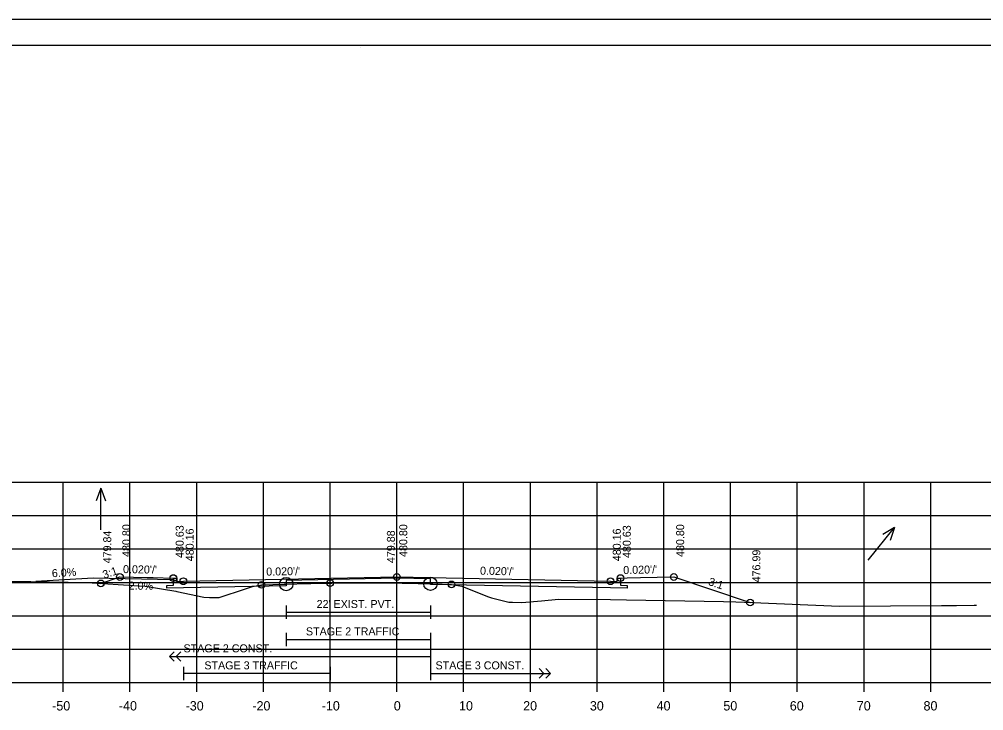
# Model space of a CAD drawing. Extents: x 1371057 to 1372761, y 380005 to 390517.
# Drawn here: x 1371504.3 to 1371648.8, y 382034.9 to 382138.5 of the extents above; entities that cross this region are included whole.
import ezdxf

# ---------------------------------------------------------------- set-up
doc = ezdxf.new("R2010")
doc.units = 0
for name, color, linetype in [('R_Alt Surface', 7, 'Continuous'), ('R_Axis', 7, 'Continuous'), ('R_Axis Annot', 7, 'Continuous'), ('R_Border', 7, 'Continuous'), ('R_Drive', 7, 'Continuous'), ('R_Exist Surface', 7, 'Continuous'), ('R_Fin Surface', 7, 'Continuous'), ('R_Grid', 7, 'Continuous'), ('R_No Plot', 7, 'Continuous'), ('R_Striping', 7, 'Continuous'), ('R_Water', 7, 'Continuous'), ('R_Water Annot', 7, 'Continuous'), ('R_Xsect Elev', 7, 'Continuous'), ('R_Xsect Slope', 7, 'Continuous')]:
    doc.layers.add(name, color=color, linetype=linetype)

msp = doc.modelspace()

# ---------------------------------------------------------------- linework, layer by layer
at = {"layer": 'R_Alt Surface'}
for points in [[(1371594.37, 382054.74), (1371594.37, 382053.66), (1371595.37, 382053.64), (1371595.37, 382053.21), (1371592.87, 382053.26), (1371565.89, 382053.8), (1371565.89, 382054.63), (1371560.87, 382054.73), (1371544.28, 382054.39), (1371544.28, 382053.56), (1371528.87, 382053.26), (1371526.37, 382053.21), (1371526.37, 382053.64), (1371527.37, 382053.66), (1371527.37, 382054.74)], [(1371594.37, 382054.74), (1371594.37, 382053.66), (1371595.37, 382053.64), (1371595.37, 382053.21), (1371592.87, 382053.26), (1371565.89, 382053.8), (1371565.89, 382054.63), (1371560.87, 382054.73), (1371544.28, 382054.39), (1371544.28, 382053.56), (1371528.87, 382053.26), (1371526.37, 382053.21), (1371526.37, 382053.64), (1371527.37, 382053.66), (1371527.37, 382054.74)], [(1371544.28, 382050.65), (1371544.28, 382048.65)], [(1371565.89, 382050.65), (1371565.89, 382048.65)], [(1371544.28, 382049.65), (1371565.89, 382049.65)]]:
    msp.add_lwpolyline(points, dxfattribs=at)
at = {"layer": 'R_Axis'}
for p, q in [((1371410.87, 382039.1), (1371710.87, 382039.1)), ((1371510.87, 382037.7), (1371510.87, 382039.1)), ((1371520.87, 382037.7), (1371520.87, 382039.1)), ((1371530.87, 382037.7), (1371530.87, 382039.1)), ((1371540.87, 382037.7), (1371540.87, 382039.1)), ((1371550.87, 382037.7), (1371550.87, 382039.1)), ((1371560.87, 382037.7), (1371560.87, 382039.1)), ((1371570.87, 382037.7), (1371570.87, 382039.1)), ((1371580.87, 382037.7), (1371580.87, 382039.1)), ((1371590.87, 382037.7), (1371590.87, 382039.1)), ((1371600.87, 382037.7), (1371600.87, 382039.1)), ((1371610.87, 382037.7), (1371610.87, 382039.1)), ((1371620.87, 382037.7), (1371620.87, 382039.1)), ((1371630.87, 382037.7), (1371630.87, 382039.1)), ((1371640.87, 382037.7), (1371640.87, 382039.1))]:
    msp.add_line(p, q, dxfattribs=at)
at = {"layer": 'R_Border'}
for p, q in [((1371402.87, 382134.56), (1371719.05, 382134.56)), ((1371555.39, 382134.3), (1371555.39, 382134.3)), ((1371555.39, 382134.3), (1371555.39, 382134.3))]:
    msp.add_line(p, q, dxfattribs=at)
at = {"layer": 'R_Drive'}
for p, q in [((1371515.38, 382054.73), (1371506.76, 382054.21)), ((1371527.38, 382054.49), (1371515.38, 382054.73)), ((1371527.88, 382054.24), (1371527.38, 382054.49))]:
    msp.add_line(p, q, dxfattribs=at)
at = {"layer": 'R_Exist Surface'}
msp.add_lwpolyline([(1371491.95, 382054.47), (1371514.43, 382054.07), (1371522.27, 382053.59), (1371523.14, 382053.54), (1371527.75, 382052.76), (1371527.87, 382052.74), (1371527.88, 382052.73), (1371527.9, 382052.73), (1371531.96, 382051.86), (1371532.79, 382051.85), (1371534.22, 382051.81), (1371538.19, 382053.15), (1371538.92, 382053.38), (1371539.24, 382053.46), (1371540.59, 382053.72), (1371543.96, 382053.83), (1371544.28, 382053.84), (1371544.37, 382053.84), (1371547.41, 382053.94), (1371547.99, 382053.95), (1371554.32, 382054.04), (1371554.41, 382054.04), (1371555.14, 382054.03), (1371555.14, 382054.03), (1371555.64, 382054.03), (1371561.66, 382053.97), (1371562.16, 382053.96), (1371565.89, 382053.88), (1371565.89, 382053.88), (1371566.25, 382053.86), (1371569.06, 382053.79), (1371570.02, 382053.64), (1371570.61, 382053.52), (1371574.43, 382052), (1371575.06, 382051.78), (1371576.06, 382051.53), (1371577.65, 382051.13), (1371578.2, 382051.12), (1371579.6, 382051.06), (1371582.52, 382051.33), (1371585.07, 382051.56), (1371592.86, 382051.54), (1371595.3, 382051.5), (1371609.81, 382051.21), (1371611.64, 382051.18), (1371614.23, 382051.07), (1371627.2, 382050.55), (1371642.46, 382050.62), (1371644.73, 382050.64), (1371647.37, 382050.68), (1371647.74, 382050.68)], dxfattribs=at)
at = {"layer": 'R_Fin Surface'}
msp.add_lwpolyline([(1371516.51, 382053.94), (1371519.37, 382054.9), (1371523.44, 382054.81), (1371524.37, 382054.8), (1371527.37, 382054.74), (1371527.79, 382054.74), (1371527.87, 382054.74), (1371527.88, 382054.24), (1371528.87, 382054.26), (1371560.87, 382054.9), (1371560.87, 382054.9), (1371560.88, 382054.9), (1371592.87, 382054.26), (1371593.21, 382054.25), (1371593.87, 382054.24), (1371593.87, 382054.49), (1371593.87, 382054.74), (1371594.17, 382054.74), (1371594.37, 382054.74), (1371595.38, 382054.76), (1371597.37, 382054.8), (1371597.37, 382054.8), (1371602.37, 382054.9), (1371602.38, 382054.9), (1371613.79, 382051.09)], dxfattribs=at)
at = {"layer": 'R_Grid'}
for p, q in [((1371410.87, 382069.1), (1371710.87, 382069.1)), ((1371510.87, 382039.1), (1371510.87, 382069.1)), ((1371520.87, 382039.1), (1371520.87, 382069.1)), ((1371530.87, 382039.1), (1371530.87, 382069.1)), ((1371540.87, 382039.1), (1371540.87, 382069.1)), ((1371550.87, 382039.1), (1371550.87, 382069.1)), ((1371560.87, 382039.1), (1371560.87, 382069.1)), ((1371570.87, 382039.1), (1371570.87, 382069.1)), ((1371580.87, 382039.1), (1371580.87, 382069.1)), ((1371590.87, 382039.1), (1371590.87, 382069.1)), ((1371600.87, 382039.1), (1371600.87, 382069.1)), ((1371610.87, 382039.1), (1371610.87, 382069.1)), ((1371620.87, 382039.1), (1371620.87, 382069.1)), ((1371630.87, 382039.1), (1371630.87, 382069.1)), ((1371640.87, 382039.1), (1371640.87, 382069.1)), ((1371410.87, 382064.1), (1371710.87, 382064.1)), ((1371410.87, 382059.1), (1371710.87, 382059.1)), ((1371410.87, 382054.1), (1371710.87, 382054.1)), ((1371410.87, 382049.1), (1371710.87, 382049.1)), ((1371410.87, 382044.1), (1371710.87, 382044.1)), ((1371410.87, 382039.1), (1371710.87, 382039.1))]:
    msp.add_line(p, q, dxfattribs=at)
at = {"layer": 'R_No Plot'}
msp.add_line((1371390.47, 382138.46), (1371723.8, 382138.46), dxfattribs=at)
for points in [[(1371390.46, 382138.46), (1371723.8, 382138.46), (1371723.8, 381925.12), (1371390.46, 381925.12)], [(1371636.79, 382134.56), (1371656.41, 382134.56), (1371656.41, 382124.68), (1371672.52, 382124.68), (1371695.72, 382124.68), (1371695.84, 382096.52), (1371719.05, 382096.52), (1371719.05, 381929.1), (1371402.87, 381929.1), (1371402.87, 382134.56)]]:
    msp.add_lwpolyline(points, close=True, dxfattribs=at)
for centre, radius in [((1371516.51, 382053.94), 0.5), ((1371519.37, 382054.9), 0.5), ((1371527.37, 382054.74), 0.5), ((1371528.87, 382054.26), 0.5), ((1371544.28, 382053.84), 1), ((1371550.87, 382053.99), 0.5), ((1371560.87, 382054.9), 0.5), ((1371565.89, 382053.88), 1), ((1371592.87, 382054.26), 0.5), ((1371594.37, 382054.74), 0.5), ((1371602.37, 382054.9), 0.5), ((1371540.59, 382053.72), 0.5), ((1371569.06, 382053.79), 0.5), ((1371613.79, 382051.09), 0.5)]:
    msp.add_circle(centre, radius, dxfattribs=at)
at = {"layer": 'R_Striping'}
for p, q in [((1371544.27, 382046.55), (1371544.27, 382044.55)), ((1371565.9, 382046.55), (1371565.9, 382039.46)), ((1371544.27, 382045.55), (1371565.9, 382045.55)), ((1371526.78, 382043.01), (1371527.49, 382043.71)), ((1371526.78, 382043.01), (1371565.9, 382043.01)), ((1371527.49, 382042.3), (1371526.78, 382043.01)), ((1371527.78, 382043.01), (1371528.49, 382043.71)), ((1371528.49, 382042.3), (1371527.78, 382043.01)), ((1371528.87, 382041.46), (1371528.87, 382039.46)), ((1371550.87, 382041.46), (1371550.87, 382039.46)), ((1371550.87, 382040.46), (1371528.87, 382040.46)), ((1371565.9, 382040.46), (1371583.9, 382040.46)), ((1371565.94, 382040.46), (1371575.94, 382040.46)), ((1371582.9, 382040.46), (1371582.2, 382041.17)), ((1371582.2, 382039.76), (1371582.9, 382040.46)), ((1371583.9, 382040.46), (1371583.2, 382041.17)), ((1371583.2, 382039.76), (1371583.9, 382040.46))]:
    msp.add_line(p, q, dxfattribs=at)
at = {"layer": 'R_Water Annot'}
for p, q in [((1371516.51, 382068.23), (1371515.81, 382066.31)), ((1371516.51, 382061.95), (1371516.51, 382068.23)), ((1371516.51, 382068.23), (1371517.21, 382066.31)), ((1371631.51, 382057.42), (1371635.44, 382062.32)), ((1371635.44, 382062.32), (1371633.69, 382061.26)), ((1371635.44, 382062.32), (1371634.78, 382060.38))]:
    msp.add_line(p, q, dxfattribs=at)
at = {"layer": 'R_Xsect Elev'}
msp.add_line((1371560.87, 382053.98), (1371560.87, 382063.98), dxfattribs=at)

# ---------------------------------------------------------------- texts
at = {"layer": 'R_Axis Annot'}
for s, p in [('-50', (1371509.21, 382034.9)), ('-40', (1371519.21, 382034.9)), ('-30', (1371529.21, 382034.9)), ('-20', (1371539.21, 382034.9)), ('-10', (1371549.61, 382034.9)), ('0', (1371560.41, 382034.9)), ('10', (1371570.18, 382034.9)), ('20', (1371579.79, 382034.9)), ('30', (1371589.79, 382034.9)), ('40', (1371599.79, 382034.9)), ('50', (1371609.79, 382034.9)), ('60', (1371619.75, 382034.9)), ('70', (1371629.79, 382034.9)), ('80', (1371639.79, 382034.9))]:
    msp.add_text(s, height=1.4, dxfattribs=at).set_placement(p)
at = {"layer": 'R_Striping'}
for s, p in [('STAGE 2 TRAFFIC', (1371547.24, 382046.15)), ('STAGE 2 CONST.', (1371528.9, 382043.61)), ('STAGE 3 TRAFFIC', (1371532.02, 382041.06)), ('STAGE 3 CONST.', (1371566.66, 382041.06))]:
    msp.add_text(s, height=1.2, dxfattribs=at).set_placement(p)
at = {"layer": 'R_Water'}
msp.add_text("22' EXIST. PVT.", height=1.2, dxfattribs=at).set_placement((1371548.84, 382050.25))
at = {"layer": 'R_Xsect Elev'}
for s, rotation, p in [('479.84', 90, (1371518.06, 382056.94)), ('480.80', 90, (1371520.92, 382057.9)), ('480.63', 90, (1371528.92, 382057.74)), ('480.16', 90, (1371530.42, 382057.26)), ('479.88', 90, (1371560.57, 382056.98)), ('480.80', 90, (1371562.42, 382057.9)), ('480.16', 90, (1371594.42, 382057.26)), ('480.63', 90, (1371595.92, 382057.74)), ('480.80', 90, (1371603.92, 382057.9)), ('476.99', 90, (1371615.34, 382054.09)), ('6.0%', 3.4336, (1371509.2, 382054.86)), ('2.0%', 358.8542, (1371520.67, 382053.02))]:
    msp.add_text(s, height=1.2, rotation=rotation, dxfattribs=at).set_placement(p)
at = {"layer": 'R_Xsect Slope'}
for s, rotation, p in [('3:1', 18.4442, (1371517, 382054.63)), ("0.020'/'", 358.8542, (1371519.82, 382055.49)), ("0.020'/'", 1.1457, (1371541.3, 382055.1)), ("0.020'/'", 358.8543, (1371573.32, 382055.25)), ("0.020'/'", 1.1457, (1371594.8, 382055.34)), ('3:1', 341.5645, (1371607.45, 382053.73))]:
    msp.add_text(s, height=1.2, rotation=rotation, dxfattribs=at).set_placement(p)

doc.saveas('drawing.dxf')
